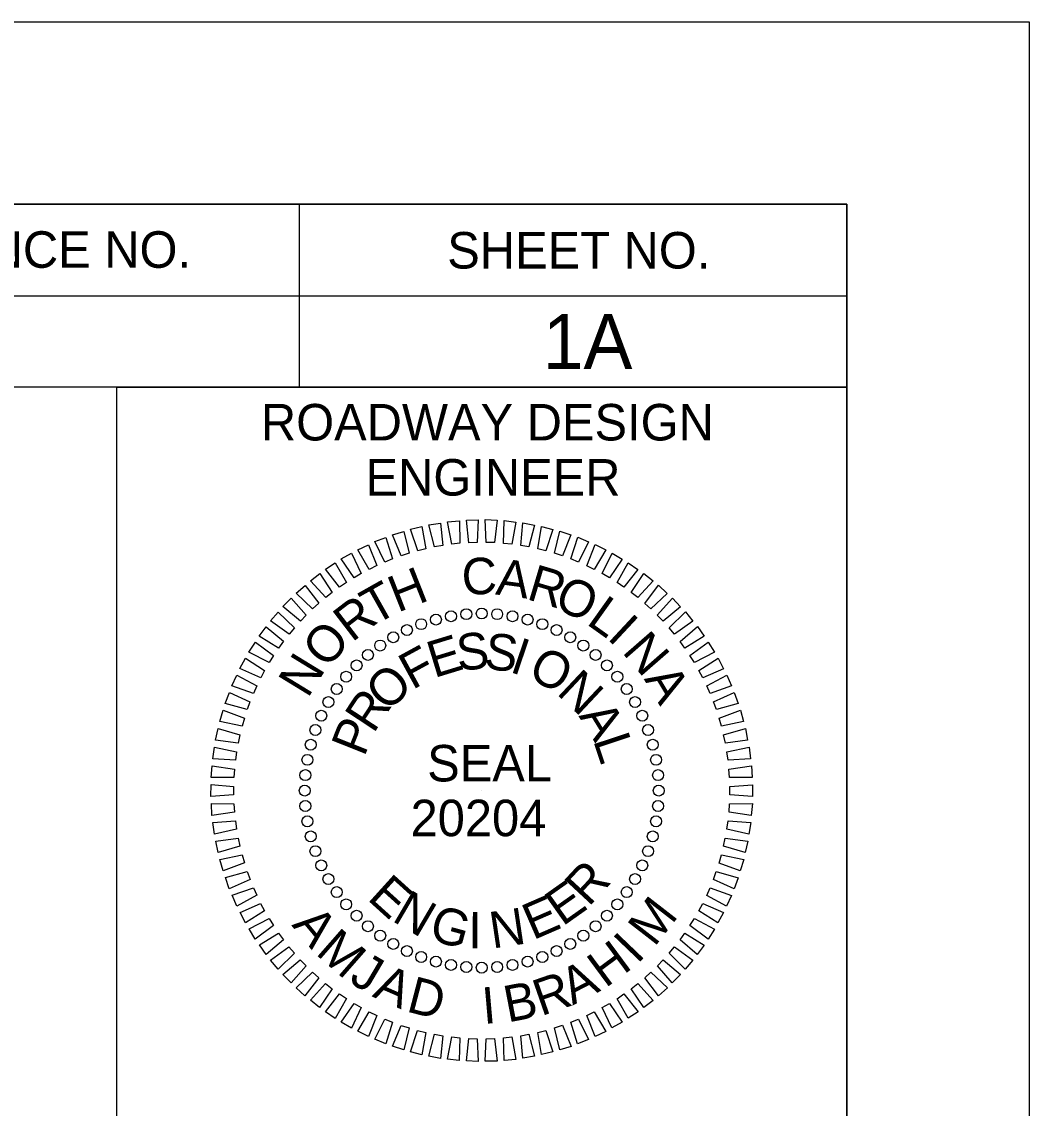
# Model space of a CAD drawing. Extents: x 885343.6 to 885383.5, y 651350.8 to 651372.8.
# Drawn here: x 885374.838 to 885377.598, y 651369.786 to 651372.762 of the extents above; entities that cross this region are included whole.
import ezdxf

# ---------------------------------------------------------------- set-up
doc = ezdxf.new("R2010")
doc.units = 0
for name, color, linetype in [('Sheet Data Field CELL', 7, 'Continuous'), ('Sheet PE Seal Cell', 7, 'Continuous'), ('Sheet Plan And Profile CELL', 7, 'Continuous'), ('Sheet Plan CELL', 7, 'Continuous'), ('Stewart Plot Border Xerox6279 and LJ5000', 7, 'Continuous')]:
    doc.layers.add(name, color=color, linetype=linetype)

msp = doc.modelspace()

# ---------------------------------------------------------------- linework, layer by layer
at = {"layer": 'Sheet PE Seal Cell'}
msp.add_line((885376.0978, 651370.6559), (885376.0978, 651370.6559), dxfattribs=at)
for points in [[(885376.0154, 651371.3307), (885376.0042, 651371.3921), (885376.0364, 651371.3949), (885376.0381, 651371.3332)], [(885376.0627, 651371.3348), (885376.0558, 651371.3968), (885376.0881, 651371.3974), (885376.0855, 651371.3358)], [(885376.1101, 651371.3356), (885376.1076, 651371.398), (885376.1398, 651371.3963), (885376.133, 651371.335)], [(885376.1575, 651371.3331), (885376.1593, 651371.3955), (885376.1914, 651371.3915), (885376.1803, 651371.3308)], [(885375.8769, 651371.2988), (885375.8532, 651371.3566), (885375.8841, 651371.366), (885375.8986, 651371.306)], [(885375.9223, 651371.3127), (885375.9026, 651371.3719), (885375.9341, 651371.3792), (885375.9444, 651371.3183)], [(885375.9685, 651371.3233), (885375.9531, 651371.3838), (885375.985, 651371.3888), (885375.991, 651371.3274)], [(885376.2046, 651371.3273), (885376.2107, 651371.3894), (885376.2425, 651371.3832), (885376.2271, 651371.3235)], [(885376.2512, 651371.3182), (885376.2616, 651371.3797), (885376.2929, 651371.3713), (885376.2734, 651371.3128)], [(885376.297, 651371.3059), (885376.3117, 651371.3665), (885376.3423, 651371.356), (885376.3188, 651371.299)], [(885375.8326, 651371.2819), (885375.8049, 651371.3378), (885375.8351, 651371.3494), (885375.8537, 651371.2906)], [(885376.3419, 651371.2904), (885376.3608, 651371.3499), (885376.3905, 651371.3372), (885376.3631, 651371.282)], [(885375.7481, 651371.2389), (885375.7128, 651371.2904), (885375.7411, 651371.306), (885375.7678, 651371.2504)], [(885375.7896, 651371.2618), (885375.758, 651371.3157), (885375.7873, 651371.3293), (885375.8101, 651371.272)], [(885376.3855, 651371.2718), (885376.4086, 651371.3298), (885376.4373, 651371.3151), (885376.4061, 651371.2619)], [(885376.4278, 651371.2503), (885376.4548, 651371.3065), (885376.4825, 651371.2899), (885376.4476, 651371.239)], [(885375.7083, 651371.213), (885375.6695, 651371.262), (885375.6966, 651371.2796), (885375.7271, 651371.2259)], [(885376.4684, 651371.2258), (885376.4993, 651371.28), (885376.5258, 651371.2615), (885376.4875, 651371.2131)], [(885375.6703, 651371.1845), (885375.6283, 651371.2306), (885375.6541, 651371.2501), (885375.6883, 651371.1987)], [(885376.5073, 651371.1985), (885376.5419, 651371.2505), (885376.567, 651371.2301), (885376.5254, 651371.1846)], [(885375.6345, 651371.1534), (885375.5893, 651371.1965), (885375.6138, 651371.2177), (885375.6514, 651371.1688)], [(885376.5442, 651371.1687), (885376.5823, 651371.2181), (885376.6059, 651371.196), (885376.5612, 651371.1535)], [(885375.6009, 651371.1199), (885375.5529, 651371.1597), (885375.5757, 651371.1825), (885375.6167, 651371.1364)], [(885376.5788, 651371.1363), (885376.6203, 651371.1829), (885376.6423, 651371.1593), (885376.5948, 651371.1199)], [(885375.5698, 651371.0841), (885375.5191, 651371.1205), (885375.5403, 651371.1448), (885375.5844, 651371.1017)], [(885376.6112, 651371.1015), (885376.6558, 651371.1452), (885376.6761, 651371.12), (885376.626, 651371.0841)], [(885375.5412, 651371.0462), (885375.4881, 651371.079), (885375.5075, 651371.1048), (885375.5545, 651371.0648)], [(885376.641, 651371.0647), (885376.6886, 651371.1051), (885376.7071, 651371.0786), (885376.6546, 651371.0463)], [(885375.5153, 651371.0064), (885375.46, 651371.0354), (885375.4777, 651371.0625), (885375.5273, 651371.0259)], [(885376.6682, 651371.0258), (885376.7185, 651371.0628), (885376.7351, 651371.035), (885376.6804, 651371.0065)], [(885375.4923, 651370.9649), (885375.4351, 651370.99), (885375.4508, 651371.0182), (885375.5029, 651370.9852)], [(885376.6926, 651370.9851), (885376.7453, 651371.0185), (885376.76, 651370.9897), (885376.7035, 651370.965)], [(885375.4722, 651370.922), (885375.4134, 651370.9429), (885375.4271, 651370.9722), (885375.4814, 651370.9429)], [(885376.7141, 651370.9428), (885376.769, 651370.9724), (885376.7817, 651370.9427), (885376.7235, 651370.922)], [(885375.4552, 651370.8777), (885375.3951, 651370.8945), (885375.4067, 651370.9247), (885375.4629, 651370.8992)], [(885376.7326, 651370.8991), (885376.7895, 651370.9248), (885376.8, 651370.8943), (885376.7406, 651370.8777)], [(885375.4413, 651370.8323), (885375.3801, 651370.8449), (885375.3896, 651370.8758), (885375.4474, 651370.8543)], [(885376.748, 651370.8542), (885376.8066, 651370.8759), (885376.8149, 651370.8447), (885376.7545, 651370.8323)], [(885375.4306, 651370.7861), (885375.3687, 651370.7944), (885375.376, 651370.8259), (885375.4352, 651370.8085)], [(885376.7603, 651370.8084), (885376.8202, 651370.8259), (885376.8263, 651370.7942), (885376.7652, 651370.7861)], [(885375.4231, 651370.7392), (885375.3608, 651370.7432), (885375.3659, 651370.7751), (885375.4261, 651370.7619)], [(885376.7693, 651370.7618), (885376.8303, 651370.7751), (885376.8342, 651370.7431), (885376.7726, 651370.7392)], [(885375.4189, 651370.6919), (885375.3565, 651370.6916), (885375.3594, 651370.7238), (885375.4204, 651370.7147)], [(885376.7751, 651370.7147), (885376.8368, 651370.7238), (885376.8385, 651370.6915), (885376.7768, 651370.6919)], [(885375.4181, 651370.6445), (885375.3558, 651370.6398), (885375.3564, 651370.6721), (885375.4179, 651370.6673)], [(885376.7775, 651370.6673), (885376.8398, 651370.672), (885376.8392, 651370.6397), (885376.7777, 651370.6445)], [(885375.4205, 651370.5971), (885375.3588, 651370.588), (885375.3571, 651370.6203), (885375.4188, 651370.6199)], [(885376.7767, 651370.6199), (885376.8391, 651370.6202), (885376.8362, 651370.588), (885376.7752, 651370.5971)], [(885375.4263, 651370.55), (885375.3653, 651370.5367), (885375.3614, 651370.5687), (885375.423, 651370.5726)], [(885376.7725, 651370.5726), (885376.8348, 651370.5686), (885376.8297, 651370.5367), (885376.7695, 651370.5499)], [(885375.4353, 651370.5034), (885375.3754, 651370.4859), (885375.3693, 651370.5176), (885375.4304, 651370.5257)], [(885376.765, 651370.5257), (885376.8269, 651370.5174), (885376.8196, 651370.4859), (885376.7604, 651370.5034)], [(885375.4476, 651370.4576), (885375.389, 651370.4359), (885375.3807, 651370.4671), (885375.4411, 651370.4795)], [(885376.7543, 651370.4795), (885376.8155, 651370.4669), (885376.806, 651370.436), (885376.7482, 651370.4575)], [(885375.463, 651370.4127), (885375.4061, 651370.387), (885375.3956, 651370.4175), (885375.455, 651370.4341)], [(885376.7404, 651370.4341), (885376.8005, 651370.4173), (885376.7889, 651370.3871), (885376.7328, 651370.4126)], [(885375.4815, 651370.369), (885375.4266, 651370.3394), (885375.4139, 651370.3691), (885375.4721, 651370.3898)], [(885376.7234, 651370.3898), (885376.7822, 651370.3689), (885376.7685, 651370.3396), (885376.7142, 651370.3689)], [(885375.503, 651370.3267), (885375.4503, 651370.2933), (885375.4356, 651370.3221), (885375.4921, 651370.3468)], [(885376.7033, 651370.3469), (885376.7605, 651370.3218), (885376.7448, 651370.2936), (885376.6927, 651370.3266)], [(885375.5274, 651370.286), (885375.4771, 651370.249), (885375.4605, 651370.2768), (885375.5152, 651370.3053)], [(885376.6803, 651370.3054), (885376.7356, 651370.2764), (885376.7179, 651370.2493), (885376.6683, 651370.2859)], [(885375.5546, 651370.2471), (885375.507, 651370.2067), (885375.4885, 651370.2332), (885375.541, 651370.2655)], [(885376.6544, 651370.2656), (885376.7075, 651370.2328), (885376.6881, 651370.207), (885376.6411, 651370.247)], [(885375.5844, 651370.2103), (885375.5398, 651370.1666), (885375.5195, 651370.1918), (885375.5696, 651370.2277)], [(885376.6258, 651370.2277), (885376.6765, 651370.1913), (885376.6553, 651370.167), (885376.6113, 651370.2101)], [(885375.6168, 651370.1755), (885375.5753, 651370.1289), (885375.5533, 651370.1525), (885375.6008, 651370.1919)], [(885376.5947, 651370.1919), (885376.6427, 651370.1521), (885376.6199, 651370.1293), (885376.5789, 651370.1754)], [(885375.6515, 651370.1431), (885375.6133, 651370.0937), (885375.5897, 651370.1158), (885375.6344, 651370.1583)], [(885376.5611, 651370.1584), (885376.6063, 651370.1153), (885376.5819, 651370.0941), (885376.5442, 651370.143)], [(885375.6883, 651370.1133), (885375.6537, 651370.0613), (885375.6286, 651370.0817), (885375.6702, 651370.1272)], [(885376.5253, 651370.1273), (885376.5673, 651370.0812), (885376.5415, 651370.0617), (885376.5073, 651370.1131)], [(885375.7272, 651370.086), (885375.6963, 651370.0318), (885375.6698, 651370.0503), (885375.7081, 651370.0987)], [(885376.4873, 651370.0988), (885376.5261, 651370.0498), (885376.499, 651370.0322), (885376.4685, 651370.0859)], [(885375.7678, 651370.0615), (885375.7408, 651370.0053), (885375.7131, 651370.0219), (885375.748, 651370.0728)], [(885376.4475, 651370.0729), (885376.4828, 651370.0214), (885376.4545, 651370.0058), (885376.4278, 651370.0614)], [(885375.8101, 651370.04), (885375.7871, 651369.982), (885375.7583, 651369.9967), (885375.7895, 651370.0499)], [(885375.8537, 651370.0214), (885375.8348, 651369.9619), (885375.8051, 651369.9746), (885375.8325, 651370.0298)], [(885376.363, 651370.0299), (885376.3907, 651369.974), (885376.3605, 651369.9624), (885376.3419, 651370.0213)], [(885376.406, 651370.05), (885376.4376, 651369.9961), (885376.4083, 651369.9825), (885376.3855, 651370.0398)], [(885375.8986, 651370.0059), (885375.8839, 651369.9453), (885375.8533, 651369.9558), (885375.8768, 651370.0128)], [(885375.9444, 651369.9936), (885375.934, 651369.9321), (885375.9027, 651369.9405), (885375.9222, 651369.999)], [(885376.2733, 651369.9991), (885376.293, 651369.9399), (885376.2615, 651369.9326), (885376.2512, 651369.9935)], [(885376.3187, 651370.013), (885376.3424, 651369.9552), (885376.3115, 651369.9458), (885376.297, 651370.0058)], [(885375.991, 651369.9845), (885375.9849, 651369.9224), (885375.9531, 651369.9286), (885375.9685, 651369.9884)], [(885376.0381, 651369.9787), (885376.0363, 651369.9163), (885376.0042, 651369.9203), (885376.0154, 651369.981)], [(885376.0855, 651369.9762), (885376.088, 651369.9138), (885376.0558, 651369.9155), (885376.0626, 651369.9768)], [(885376.1329, 651369.977), (885376.1398, 651369.915), (885376.1075, 651369.9144), (885376.1101, 651369.976)], [(885376.1802, 651369.9811), (885376.1914, 651369.9197), (885376.1592, 651369.9169), (885376.1575, 651369.9786)], [(885376.2271, 651369.9885), (885376.2425, 651369.928), (885376.2106, 651369.923), (885376.2046, 651369.9844)]]:
    msp.add_lwpolyline(points, close=True, dxfattribs=at)
for centre in [(885375.9319, 651371.1117), (885375.9723, 651371.1244), (885376.0136, 651371.1335), (885376.0555, 651371.1391), (885376.0978, 651371.1409), (885376.1401, 651371.1391), (885376.182, 651371.1335), (885376.2233, 651371.1244), (885376.2637, 651371.1117), (885375.8928, 651371.0955), (885376.3028, 651371.0955), (885375.8196, 651371.0532), (885375.8553, 651371.0759), (885376.3403, 651371.0759), (885376.376, 651371.0532), (885375.786, 651371.0274), (885376.4096, 651371.0274), (885375.7549, 651370.9988), (885376.4407, 651370.9988), (885375.7263, 651370.9677), (885376.4693, 651370.9677), (885375.7005, 651370.9341), (885376.4951, 651370.9341), (885375.6778, 651370.8984), (885376.5178, 651370.8984), (885375.6582, 651370.8609), (885376.5374, 651370.8609), (885375.6421, 651370.8218), (885376.5536, 651370.8218), (885375.6293, 651370.7814), (885376.5663, 651370.7814), (885375.6202, 651370.7401), (885376.5754, 651370.7401), (885375.6146, 651370.6982), (885376.581, 651370.6982), (885375.6128, 651370.6559), (885376.5828, 651370.6559), (885375.6146, 651370.6136), (885376.581, 651370.6136), (885375.6202, 651370.5717), (885376.5754, 651370.5717), (885375.6293, 651370.5304), (885376.5663, 651370.5304), (885375.6421, 651370.49), (885376.5536, 651370.49), (885375.6582, 651370.4509), (885376.5374, 651370.4509), (885375.6778, 651370.4134), (885376.5178, 651370.4134), (885375.7005, 651370.3777), (885376.4951, 651370.3777), (885375.7263, 651370.3441), (885376.4693, 651370.3441), (885375.7549, 651370.313), (885376.4407, 651370.313), (885375.786, 651370.2844), (885376.4096, 651370.2844), (885375.8196, 651370.2586), (885376.376, 651370.2586), (885375.8553, 651370.2359), (885376.3403, 651370.2359), (885375.8928, 651370.2163), (885375.9319, 651370.2001), (885376.2637, 651370.2001), (885376.3028, 651370.2163), (885375.9723, 651370.1874), (885376.0136, 651370.1783), (885376.0555, 651370.1727), (885376.0978, 651370.1709), (885376.1401, 651370.1727), (885376.182, 651370.1783), (885376.2233, 651370.1874)]:
    msp.add_circle(centre, 0.015, dxfattribs=at)
at = {"layer": 'Sheet Plan And Profile CELL'}
for p, q in [((885375.5978, 651372.2609), (885375.5978, 651371.7609)), ((885373.0978, 651372.0109), (885377.0978, 651372.0109))]:
    msp.add_line(p, q, dxfattribs=at)
for points in [[(885373.0978, 651372.2619), (885377.0978, 651372.2619), (885377.0978, 651371.7609), (885373.0978, 651371.7609)], [(885375.0978, 651371.7609), (885377.0978, 651371.7609), (885377.0978, 651369.5109), (885375.0978, 651369.5109)]]:
    msp.add_lwpolyline(points, close=True, dxfattribs=at)
at = {"layer": 'Sheet Plan CELL'}
msp.add_lwpolyline([(885377.0978, 651372.2619), (885347.0978, 651372.2619), (885347.0978, 651351.2619), (885377.0978, 651351.2619)], close=True, dxfattribs=at)
at = {"layer": 'Stewart Plot Border Xerox6279 and LJ5000'}
msp.add_lwpolyline([(885343.5978, 651372.7619), (885377.5978, 651372.7619), (885377.5978, 651350.7619), (885343.5978, 651350.7619)], close=True, dxfattribs=at)

# ---------------------------------------------------------------- texts
at = {"layer": 'Sheet Data Field CELL'}
msp.add_text('1A', height=0.15, rotation=0, dxfattribs=at).set_placement((885376.2651, 651371.8109))
at = {"layer": 'Sheet PE Seal Cell'}
for s, rotation, p in [('C', 1.9618, (885376.0444, 651371.1919)), ('A', 352.4568, (885376.1337, 651371.1933)), ('H', 21.601, (885375.8674, 651371.1428)), ('R', 343.4093, (885376.2177, 651371.181)), ('T', 29.3903, (885375.8035, 651371.107)), ('O', 335.2006, (885376.2915, 651371.1585)), ('L', 324.4755, (885376.3816, 651371.1137)), ('R', 37.5989, (885375.7421, 651371.0604)), ('I', 317.0103, (885376.4387, 651371.0729)), ('O', 48.3241, (885375.6731, 651370.9872)), ('E', 16.986, (885375.9672, 651370.9637)), ('S', 5.2237, (885376.0327, 651370.9838)), ('S', 353.2648, (885376.102, 651370.9902)), ('I', 341.3058, (885376.1712, 651370.9821)), ('N', 311.0704, (885376.48, 651371.0354)), ('F', 28.6639, (885375.9076, 651370.9309)), ('O', 332.5504, (885376.22, 651370.9671)), ('N', 58.5345, (885375.6211, 651370.9066)), ('O', 44.4727, (885375.8399, 651370.8686)), ('N', 316.7416, (885376.3002, 651370.922)), ('A', 300.8599, (885376.5413, 651370.9617)), ('R', 56.5721, (885375.801, 651370.8099)), ('A', 301.6915, (885376.3623, 651370.8604)), ('P', 68.3344, (885375.7759, 651370.7461)), ('L', 288.3556, (885376.4024, 651370.7938)), ('SEAL', 360, (885375.9483, 651370.6809)), ('20204', 360, (885375.9028, 651370.5309)), ('R', 47.043, (885376.3905, 651370.3356)), ('E', 317.8506, (885375.7816, 651370.3587)), ('E', 35.2807, (885376.319, 651370.2826)), ('N', 329.6129, (885375.8488, 651370.3005)), ('E', 23.5185, (885376.2383, 651370.2454)), ('M', 52.1895, (885376.5706, 651370.2253)), ('G', 344.6629, (885375.9497, 651370.2481)), ('I', 359.713, (885376.0606, 651370.2236)), ('N', 8.4684, (885376.1269, 651370.223)), ('A', 309.7469, (885375.5755, 651370.287)), ('M', 318.7944, (885375.64, 651370.2094)), ('I', 46.2495, (885376.5235, 651370.1787)), ('H', 36.4966, (885376.4365, 651370.1135)), ('J', 329.5005, (885375.7309, 651370.1322)), ('A', 27.4491, (885376.347, 651370.067)), ('A', 336.3384, (885375.7958, 651370.0922)), ('D', 345.3859, (885375.8883, 651370.0517)), ('R', 19.2405, (885376.2604, 651370.0374)), ('I', 4.9584, (885376.1028, 651370.0164)), ('B', 10.8984, (885376.1689, 651370.0204))]:
    msp.add_text(s, height=0.1, rotation=rotation, dxfattribs=at).set_placement(p)
at = {"layer": 'Sheet Plan And Profile CELL'}
for s, height, p in [('PROJECT REFERENCE NO.', 0.100002, (885373.5405, 651372.0879)), ('SHEET NO.', 0.1, (885376.0033, 651372.0859)), ('ROADWAY DESIGN', 0.100002, (885375.4928, 651371.6149)), ('ENGINEER', 0.1, (885375.7794, 651371.4639))]:
    msp.add_text(s, height=height, rotation=0, dxfattribs=at).set_placement(p)

doc.saveas('drawing.dxf')
